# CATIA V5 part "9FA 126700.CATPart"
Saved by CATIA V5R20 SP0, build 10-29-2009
Part number: 9FA 126700
Revision: ANY
Definition: UNKNOWN
Nomenclature: 9FA 126700
Source: Unknown
Bounding box of the stored display mesh (mm): x -5.85 to 5.85, y -10 to 10, z -6 to 6
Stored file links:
  C:\Users\Utente\Desktop\IO LAVORO\3D X SITO CF\CUMSA\3D files FA\FA 126700\9FA 126700.CATPart
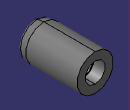
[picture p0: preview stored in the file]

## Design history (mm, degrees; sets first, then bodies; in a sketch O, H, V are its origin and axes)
Body1 "Redondeo2" (main body)
  Solid1: solid without history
